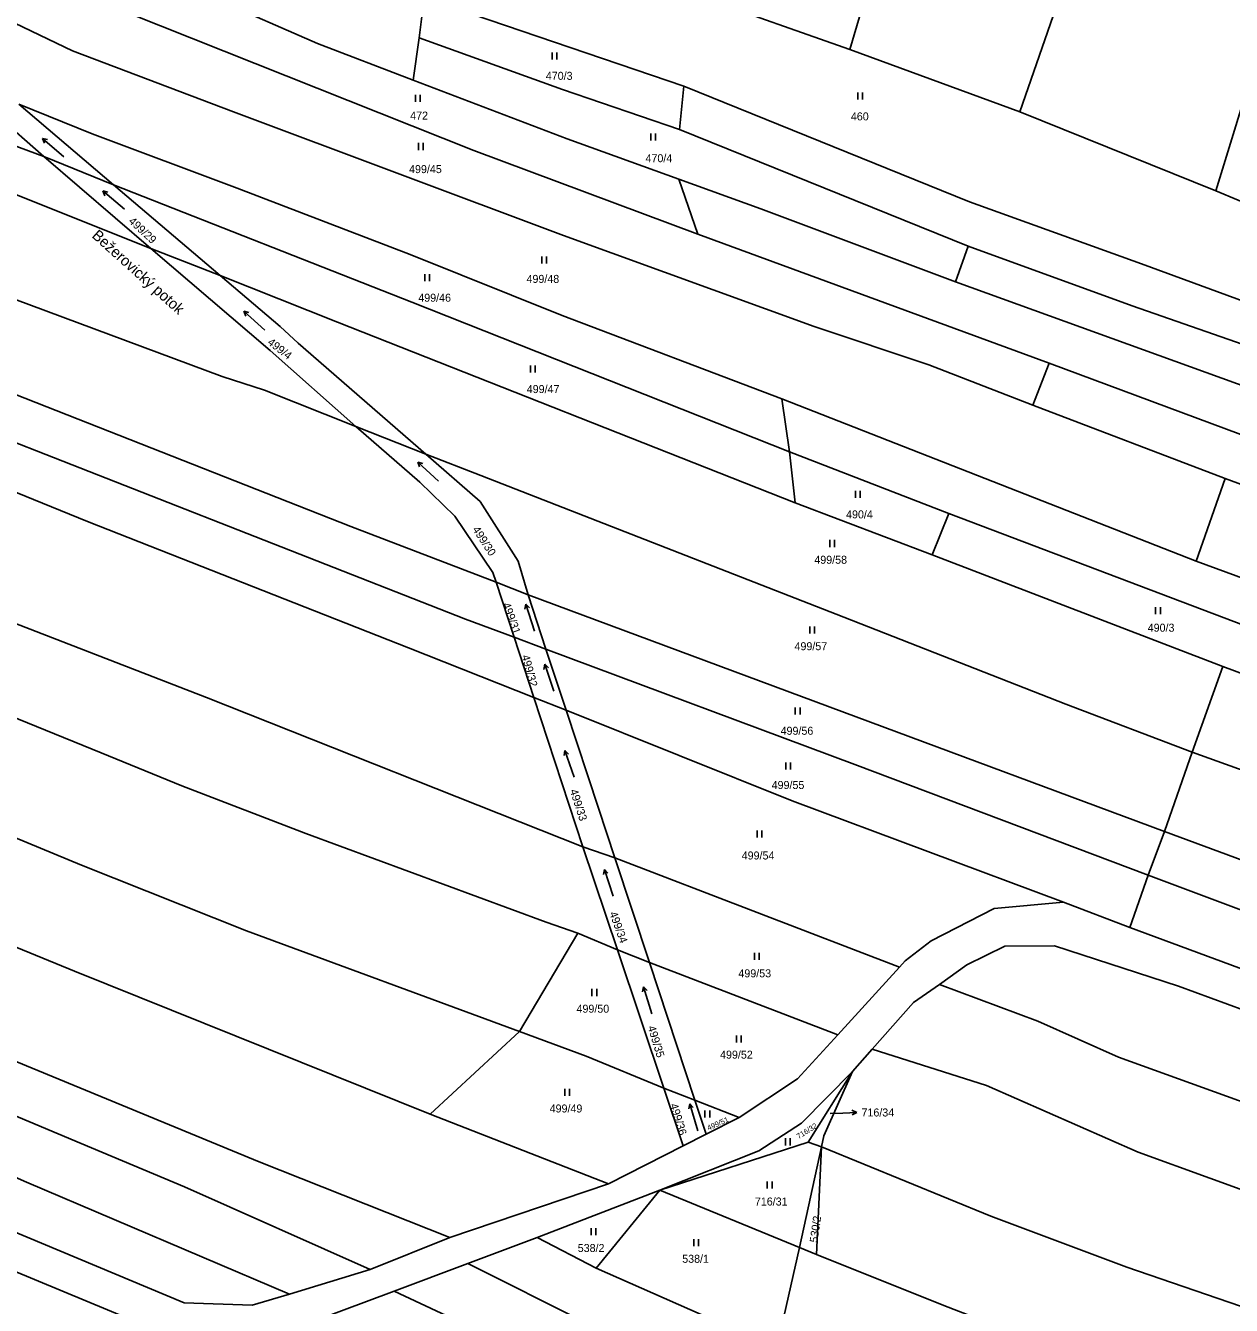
# Model space of a CAD drawing. Extents: x -7476540 to -746055, y -11317203 to -1129777.
# Drawn here: x -748441 to -748184.6, y -1130874.9 to -1130603 of the extents above; entities that cross this region are included whole.
import ezdxf

# ---------------------------------------------------------------- set-up
doc = ezdxf.new("R2010")
doc.units = 0
for name, color, linetype in [('Hranice parcel', 7, 'Continuous'), ('Parcelní čísla', 7, 'Continuous'), ('Pop  PČ popisy', 7, 'Continuous'), ('Značky kultur', 7, 'Continuous')]:
    doc.layers.add(name, color=color, linetype=linetype)

msp = doc.modelspace()

# ---------------------------------------------------------------- linework, layer by layer
at = {"layer": 'Hranice parcel'}
for p, q in [((-748306.94, -1130593.5), (-748265.75, -1130608.04)), ((-748357.28, -1130605.56), (-748356.21, -1130597)), ((-748356.21, -1130597), (-748301.06, -1130615.84)), ((-748358.56, -1130614.59), (-748357.28, -1130605.56)), ((-748265.75, -1130608.04), (-748229.57, -1130621.28)), ((-748455.69, -1130614.55), (-748437.09, -1130630.78)), ((-748301.06, -1130615.84), (-748301.92, -1130625.04)), ((-748422.31, -1130636.78), (-748442.43, -1130619.67)), ((-748229.57, -1130621.28), (-748187.91, -1130638.09)), ((-748301.92, -1130625.04), (-748240.56, -1130649.85)), ((-748437.09, -1130630.78), (-748422.31, -1130636.78)), ((-748437.09, -1130630.78), (-748414.36, -1130650.31)), ((-748399.6, -1130656.07), (-748422.31, -1130636.78)), ((-748302.08, -1130635.58), (-748298.06, -1130647.31)), ((-748187.91, -1130638.09), (-748171.3, -1130645.09)), ((-748298.06, -1130647.31), (-748223.38, -1130674.7)), ((-748399.6, -1130656.07), (-748414.36, -1130650.31)), ((-748240.56, -1130649.85), (-748243.24, -1130657.42)), ((-748223.38, -1130674.7), (-748226.83, -1130683.61)), ((-748192.08, -1130716.76), (-748280.18, -1130682.27)), ((-748280.18, -1130682.27), (-748278.6, -1130693.52)), ((-748226.83, -1130683.61), (-748185.93, -1130699.2)), ((-748370.74, -1130688.16), (-748355.87, -1130694.01)), ((-748278.6, -1130693.52), (-748244.7, -1130706.67)), ((-748278.6, -1130693.52), (-748277.39, -1130704.35)), ((-748185.93, -1130699.2), (-748192.08, -1130716.76)), ((-748277.39, -1130704.35), (-748248.26, -1130715.42)), ((-748244.7, -1130706.67), (-748248.26, -1130715.42)), ((-748248.26, -1130715.42), (-748186.46, -1130739.14)), ((-748340.95, -1130721.23), (-748334.14, -1130723.95)), ((-748340.95, -1130721.23), (-748337.1, -1130732.95)), ((-748330.34, -1130735.47), (-748334.14, -1130723.95)), ((-748337.1, -1130732.95), (-748330.34, -1130735.47)), ((-748337.1, -1130732.95), (-748332.9, -1130745.74)), ((-748326.07, -1130748.44), (-748330.34, -1130735.47)), ((-748186.46, -1130739.14), (-748192.95, -1130757.36)), ((-748186.46, -1130739.14), (-748156.81, -1130750.21)), ((-748332.9, -1130745.74), (-748326.07, -1130748.44)), ((-748322.49, -1130777.44), (-748332.9, -1130745.74)), ((-748198.84, -1130774.24), (-748192.95, -1130757.36)), ((-748202.3, -1130783.51), (-748198.84, -1130774.24)), ((-748322.49, -1130777.44), (-748315.72, -1130779.81)), ((-748322.49, -1130777.44), (-748315.11, -1130799.35)), ((-748308.36, -1130802.04), (-748315.72, -1130779.81)), ((-748255.16, -1130803.06), (-748315.72, -1130779.81)), ((-748206.22, -1130794.61), (-748202.3, -1130783.51)), ((-748206.22, -1130794.61), (-748220.29, -1130789.23)), ((-748323.6, -1130795.85), (-748336, -1130816.73)), ((-748323.6, -1130795.85), (-748315.11, -1130799.35)), ((-748315.11, -1130799.35), (-748308.36, -1130802.04)), ((-748315.11, -1130799.35), (-748305.32, -1130828.72)), ((-748298.68, -1130831.28), (-748308.36, -1130802.04)), ((-748268.27, -1130817.4), (-748308.36, -1130802.04)), ((-748255.16, -1130803.06), (-748268.27, -1130817.4)), ((-748336, -1130816.73), (-748354.99, -1130834.29)), ((-748260.98, -1130820.46), (-748265.19, -1130825.19)), ((-748274.62, -1130840.2), (-748265.19, -1130825.19)), ((-748305.32, -1130828.72), (-748298.68, -1130831.28)), ((-748305.32, -1130828.72), (-748301.18, -1130841.02)), ((-748296.28, -1130838.54), (-748298.68, -1130831.28)), ((-748289.25, -1130834.98), (-748298.68, -1130831.28)), ((-748354.99, -1130834.29), (-748317.07, -1130849.07)), ((-748289.25, -1130834.98), (-748296.28, -1130838.54)), ((-748296.28, -1130838.54), (-748301.18, -1130841.02)), ((-748301.18, -1130841.02), (-748317.07, -1130849.07)), ((-748274.62, -1130840.2), (-748306.12, -1130850.42)), ((-748271.76, -1130841.22), (-748276.46, -1130862.6)), ((-748271.76, -1130841.22), (-748274.62, -1130840.2)), ((-748272.8, -1130864.07), (-748271.76, -1130841.22)), ((-748317.07, -1130849.07), (-748350.77, -1130860.5)), ((-748332.19, -1130860.47), (-748306.12, -1130850.42)), ((-748306.12, -1130850.42), (-748319.69, -1130866.98)), ((-748276.46, -1130862.6), (-748306.12, -1130850.42)), ((-748350.77, -1130860.5), (-748367.71, -1130867.32)), ((-748346.93, -1130865.99), (-748332.19, -1130860.47)), ((-748319.69, -1130866.98), (-748332.19, -1130860.47)), ((-748276.46, -1130862.6), (-748281.3, -1130883.89)), ((-748276.46, -1130862.6), (-748272.8, -1130864.07)), ((-748362.61, -1130871.86), (-748346.93, -1130865.99)), ((-748367.71, -1130867.32), (-748384.89, -1130872.51)), ((-748281.3, -1130883.89), (-748319.69, -1130866.98)), ((-748379.12, -1130878.04), (-748362.61, -1130871.86))]:
    msp.add_line(p, q, dxfattribs=at)
for points in [[(-748265.75, -1130608.04), (-748247.9, -1130547.61), (-748233.17, -1130503.73)], [(-748229.57, -1130621.28), (-748216.56, -1130583.68), (-748204.16, -1130547.99), (-748197.06, -1130528.56)], [(-748187.91, -1130638.09), (-748178.92, -1130608.81), (-748161.77, -1130554.58)], [(-748485.04, -1130582.73), (-748469.61, -1130589.74), (-748431.04, -1130608.33), (-748396.79, -1130621.28), (-748326.64, -1130647.59), (-748273.31, -1130666.87), (-748248.94, -1130675.02), (-748226.83, -1130683.61)], [(-748400.65, -1130597.24), (-748378.93, -1130606.77), (-748358.56, -1130614.59)], [(-748418.92, -1130600.37), (-748345.69, -1130629.51), (-748298.06, -1130647.31)], [(-748370.74, -1130688.16), (-748390.16, -1130680.44), (-748399.18, -1130677.54), (-748453.71, -1130657.26), (-748528.86, -1130627.98), (-748582.3, -1130606.18)], [(-748357.28, -1130605.56), (-748326.8, -1130616.53), (-748301.92, -1130625.04)], [(-748474.99, -1130628.2), (-748478.16, -1130615.62), (-748437.09, -1130630.78)], [(-748358.56, -1130614.59), (-748325.84, -1130627.02), (-748302.08, -1130635.58)], [(-748301.06, -1130615.84), (-748240.31, -1130640.44), (-748203.71, -1130653.58), (-748161.84, -1130668.98)], [(-748280.18, -1130682.27), (-748326.88, -1130664.57), (-748359.23, -1130651.59), (-748396.02, -1130637.54), (-748426.83, -1130625.94), (-748442.43, -1130619.67)], [(-748340.95, -1130721.23), (-748371.81, -1130709.41), (-748485.85, -1130664.58), (-748534.39, -1130645.25), (-748586.34, -1130622.61)], [(-748414.36, -1130650.31), (-748452.93, -1130634.95), (-748474.99, -1130628.2)], [(-748337.1, -1130732.95), (-748347.47, -1130729.08), (-748459.12, -1130685.32), (-748534.17, -1130654.92), (-748588.68, -1130630.55)], [(-748422.31, -1130636.78), (-748358.85, -1130661.76), (-748278.6, -1130693.52)], [(-748302.08, -1130635.58), (-748284.66, -1130641.91), (-748243.24, -1130657.42)], [(-748332.9, -1130745.74), (-748359.6, -1130735.19), (-748427.81, -1130708.36), (-748542.83, -1130661.55), (-748593.74, -1130637.98)], [(-748414.36, -1130650.31), (-748389.01, -1130672.04), (-748370.74, -1130688.16)], [(-748240.56, -1130649.85), (-748205.74, -1130662.52), (-748166.46, -1130676.19), (-748149.75, -1130682.7), (-748123.01, -1130692.38), (-748074.3, -1130710.72), (-748054.6, -1130717.75), (-748018.25, -1130732.85), (-747986.44, -1130749.26)], [(-748399.6, -1130656.07), (-748374.67, -1130665.95), (-748277.39, -1130704.35)], [(-748355.87, -1130694.01), (-748383.04, -1130670.46), (-748386.85, -1130666.91), (-748399.6, -1130656.07)], [(-748243.24, -1130657.42), (-748166.65, -1130685.11), (-748094.37, -1130712.93), (-748058.72, -1130726.42), (-748019.1, -1130743.55), (-747990.16, -1130757.72)], [(-748606.79, -1130664), (-748593.41, -1130669.82), (-748555.79, -1130686.41), (-748521.14, -1130699.97), (-748463.67, -1130722.09), (-748402.55, -1130745.71), (-748322.49, -1130777.44)], [(-748223.38, -1130674.7), (-748160.68, -1130697.99), (-748104.99, -1130718.13), (-748087.93, -1130725.07), (-748056.46, -1130736.89), (-748027.2, -1130749.04), (-747994, -1130766.24)], [(-748370.74, -1130688.16), (-748357.13, -1130699.98), (-748349.74, -1130707.22), (-748341.63, -1130719.17), (-748340.95, -1130721.23)], [(-748591.33, -1130689.59), (-748556.18, -1130705.09), (-748511.54, -1130723.13), (-748468.11, -1130739.92), (-748424.93, -1130757.48), (-748407.79, -1130764.49), (-748381.4, -1130774.63), (-748330.32, -1130793.51), (-748323.6, -1130795.85)], [(-748334.14, -1130723.95), (-748336.28, -1130716.76), (-748344.32, -1130704.11), (-748355.87, -1130694.01)], [(-748192.95, -1130757.36), (-748219.82, -1130747.15), (-748267.04, -1130728.69), (-748344.18, -1130698.6), (-748355.87, -1130694.01)], [(-748185.93, -1130699.2), (-748116.35, -1130724.81), (-748065.1, -1130743.37), (-748028.39, -1130758.32), (-747998.62, -1130776.08)], [(-748244.7, -1130706.67), (-748172.71, -1130733.91), (-748157.04, -1130739.82)], [(-748600.62, -1130708.93), (-748572.02, -1130722.05), (-748553.57, -1130730.11), (-748529.63, -1130739.69), (-748429.06, -1130781.38), (-748394.01, -1130795.35), (-748336, -1130816.73)], [(-748192.08, -1130716.76), (-748141.67, -1130735.26), (-748110.72, -1130746.5), (-748083.73, -1130756.86), (-748044.13, -1130772.48), (-748036.15, -1130775.89), (-748006.3, -1130791.42)], [(-748198.84, -1130774.24), (-748264.42, -1130749.83), (-748334.14, -1130723.95)], [(-748609.37, -1130729.04), (-748586.47, -1130739.97), (-748565.25, -1130748.92), (-748478.86, -1130784.11), (-748430.59, -1130803.91), (-748354.99, -1130834.29)], [(-748202.3, -1130783.51), (-748264.68, -1130759.98), (-748330.34, -1130735.47)], [(-748617.75, -1130748.36), (-748594.66, -1130762.19), (-748574.85, -1130769.98), (-748508.41, -1130796.48), (-748448.56, -1130820.81), (-748391.34, -1130844.41), (-748350.77, -1130860.5)], [(-748315.72, -1130779.81), (-748319.21, -1130769.27), (-748326.07, -1130748.44)], [(-748220.29, -1130789.23), (-748278.03, -1130767.72), (-748326.07, -1130748.44)], [(-748638.72, -1130751.72), (-748602.16, -1130770.3), (-748522.97, -1130802.41), (-748472.42, -1130822.39), (-748429.14, -1130840.54), (-748407.16, -1130849.74), (-748367.71, -1130867.32)], [(-748192.95, -1130757.36), (-748149.26, -1130773.11), (-748117.42, -1130785.04), (-748079.7, -1130799.19), (-748023.6, -1130824.38)], [(-748641.83, -1130766.14), (-748594.17, -1130785.58), (-748542.67, -1130805.9), (-748476.15, -1130833.14), (-748440.81, -1130848.76), (-748384.89, -1130872.51)], [(-748384.89, -1130872.51), (-748392.79, -1130874.89), (-748407.29, -1130874.39), (-748504.41, -1130833.78), (-748556.44, -1130811.2), (-748636.94, -1130777.36), (-748641.83, -1130766.14)], [(-748198.84, -1130774.24), (-748124.83, -1130801.55), (-748095.68, -1130812.38), (-748052.4, -1130830.31), (-748030.93, -1130840.93)], [(-748202.3, -1130783.51), (-748146.21, -1130804.55), (-748090.95, -1130825.26), (-748056.18, -1130839.2), (-748035.09, -1130849.72)], [(-748640.02, -1130785.32), (-748543.51, -1130825.81), (-748464.71, -1130858.77), (-748407.23, -1130882.69)], [(-748220.29, -1130789.23), (-748235.03, -1130790.57), (-748248.44, -1130797.43), (-748253.94, -1130801.72), (-748255.16, -1130803.06)], [(-748042.25, -1130857.8), (-748097.77, -1130834.89), (-748116.18, -1130827.89), (-748206.22, -1130794.61)], [(-748246.71, -1130806.7), (-748240.86, -1130802.57), (-748232.82, -1130798.59), (-748222.25, -1130798.5), (-748195.87, -1130807.09), (-748171.55, -1130816.01), (-748091.95, -1130844.69), (-748061.9, -1130856.72), (-748042.73, -1130867.52)], [(-748260.98, -1130820.46), (-748252.18, -1130810.57), (-748246.71, -1130806.7)], [(-748037.84, -1130894.2), (-748054.55, -1130885.78), (-748102.13, -1130862.63), (-748153.66, -1130841.78), (-748178, -1130833.24), (-748208.63, -1130822.17), (-748225.74, -1130814.53), (-748246.71, -1130806.7)], [(-748305.32, -1130828.72), (-748321.79, -1130821.98), (-748336, -1130816.73)], [(-748268.27, -1130817.4), (-748276.84, -1130826.78), (-748289.25, -1130834.98)], [(-748027.06, -1130916.24), (-748075.79, -1130892.9), (-748112.36, -1130877.79), (-748129.42, -1130870.81), (-748173.97, -1130853.4), (-748204.44, -1130842.38), (-748236.71, -1130828.16), (-748260.98, -1130820.46)], [(-748306.12, -1130850.42), (-748285.08, -1130842.06), (-748276.01, -1130836.18), (-748265.19, -1130825.19)], [(-748265.19, -1130825.19), (-748271.25, -1130838.88), (-748271.76, -1130841.22)], [(-748271.76, -1130841.22), (-748235.77, -1130855.93), (-748206.84, -1130866.81), (-748165.74, -1130880.87), (-748130.12, -1130894.99), (-748094.02, -1130910.31), (-748045.92, -1130930.72), (-748002.03, -1130951.62), (-747975.69, -1130968.08), (-747956.74, -1130979.41)], [(-748283.22, -1130895.4), (-748321.83, -1130878.64), (-748346.93, -1130865.99)], [(-747973.45, -1130994.17), (-747986.3, -1130986.83), (-748025.01, -1130962.88), (-748060.2, -1130946.83), (-748098.9, -1130931.91), (-748130.17, -1130918.61), (-748198.42, -1130893.2), (-748245.75, -1130874.96), (-748272.8, -1130864.07)], [(-748285.26, -1130906.35), (-748321.46, -1130891.15), (-748362.61, -1130871.86)]]:
    msp.add_lwpolyline(points, dxfattribs=at)
at = {"layer": 'Pop  PČ popisy'}
for p, q in [((-748269.9, -1130834.17), (-748267.26, -1130834.05)), ((-748267.26, -1130834.05), (-748264.26, -1130833.89)), ((-748264.26, -1130833.89), (-748265.29, -1130833.45)), ((-748264.26, -1130833.89), (-748265.24, -1130834.45))]:
    msp.add_line(p, q, dxfattribs=at)
at = {"layer": 'Značky kultur'}
for p, q in [((-748329, -1130610.17), (-748329, -1130608.67)), ((-748328, -1130610.17), (-748328, -1130608.67)), ((-748358.11, -1130619.19), (-748358.11, -1130617.69)), ((-748357.11, -1130619.19), (-748357.11, -1130617.69)), ((-748264.03, -1130618.7), (-748264.03, -1130617.2)), ((-748263.03, -1130618.7), (-748263.03, -1130617.2)), ((-748308.08, -1130627.38), (-748308.08, -1130625.88)), ((-748307.08, -1130627.38), (-748307.08, -1130625.88)), ((-748432.86, -1130630.87), (-748437.39, -1130626.93)), ((-748437.39, -1130626.93), (-748436.98, -1130627.95)), ((-748437.39, -1130626.93), (-748436.33, -1130627.2)), ((-748357.48, -1130629.4), (-748357.48, -1130627.9)), ((-748356.48, -1130629.4), (-748356.48, -1130627.9)), ((-748419.96, -1130641.96), (-748424.56, -1130638.1)), ((-748424.56, -1130638.1), (-748424.13, -1130639.12)), ((-748424.56, -1130638.1), (-748423.48, -1130638.35)), ((-748331.23, -1130653.52), (-748331.23, -1130652.02)), ((-748330.23, -1130653.52), (-748330.23, -1130652.02)), ((-748356.1, -1130657.3), (-748356.1, -1130655.8)), ((-748355.1, -1130657.3), (-748355.1, -1130655.8)), ((-748390.12, -1130667.69), (-748394.58, -1130663.68)), ((-748394.58, -1130663.68), (-748394.19, -1130664.7)), ((-748394.58, -1130663.68), (-748393.52, -1130663.96)), ((-748333.62, -1130676.71), (-748333.62, -1130675.21)), ((-748332.62, -1130676.71), (-748332.62, -1130675.21)), ((-748353.2, -1130699.79), (-748357.59, -1130695.7)), ((-748357.59, -1130695.7), (-748357.22, -1130696.73)), ((-748357.59, -1130695.7), (-748356.53, -1130696)), ((-748264.57, -1130703.34), (-748264.57, -1130701.84)), ((-748263.57, -1130703.34), (-748263.57, -1130701.84)), ((-748270, -1130713.77), (-748270, -1130712.27)), ((-748269, -1130713.77), (-748269, -1130712.27)), ((-748334.65, -1130725.92), (-748334.83, -1130727)), ((-748332.8, -1130731.62), (-748334.65, -1130725.92)), ((-748334.65, -1130725.92), (-748333.88, -1130726.69)), ((-748200.72, -1130728.01), (-748200.72, -1130726.51)), ((-748199.72, -1130728.01), (-748199.72, -1130726.51)), ((-748274.27, -1130732.14), (-748274.27, -1130730.64)), ((-748273.27, -1130732.14), (-748273.27, -1130730.64)), ((-748330.62, -1130738.69), (-748330.78, -1130739.78)), ((-748328.67, -1130744.37), (-748330.62, -1130738.69)), ((-748330.62, -1130738.69), (-748329.83, -1130739.46)), ((-748277.33, -1130749.33), (-748277.33, -1130747.83)), ((-748276.33, -1130749.33), (-748276.33, -1130747.83)), ((-748326.33, -1130756.98), (-748326.49, -1130758.07)), ((-748324.38, -1130762.66), (-748326.33, -1130756.98)), ((-748326.33, -1130756.98), (-748325.54, -1130757.75)), ((-748279.34, -1130761.04), (-748279.34, -1130759.54)), ((-748278.34, -1130761.04), (-748278.34, -1130759.54)), ((-748285.46, -1130775.52), (-748285.46, -1130774.02)), ((-748284.46, -1130775.52), (-748284.46, -1130774.02)), ((-748317.93, -1130782.27), (-748318.11, -1130783.35)), ((-748316.08, -1130787.97), (-748317.93, -1130782.27)), ((-748317.93, -1130782.27), (-748317.16, -1130783.04)), ((-748286.01, -1130801.5), (-748286.01, -1130800)), ((-748285.01, -1130801.5), (-748285.01, -1130800)), ((-748320.56, -1130809.17), (-748320.56, -1130807.67)), ((-748319.56, -1130809.17), (-748319.56, -1130807.67)), ((-748309.59, -1130807.23), (-748309.79, -1130808.31)), ((-748307.84, -1130812.97), (-748309.59, -1130807.23)), ((-748309.59, -1130807.23), (-748308.83, -1130808.02)), ((-748289.81, -1130819.04), (-748289.81, -1130817.54)), ((-748288.81, -1130819.04), (-748288.81, -1130817.54)), ((-748326.34, -1130830.37), (-748326.34, -1130828.87)), ((-748325.34, -1130830.37), (-748325.34, -1130828.87)), ((-748299.79, -1130832.07), (-748299.99, -1130833.15)), ((-748298.04, -1130837.81), (-748299.79, -1130832.07)), ((-748299.79, -1130832.07), (-748299.03, -1130832.86)), ((-748296.54, -1130835), (-748296.54, -1130833.5)), ((-748295.54, -1130835), (-748295.54, -1130833.5)), ((-748279.43, -1130840.91), (-748279.43, -1130839.41)), ((-748278.43, -1130840.91), (-748278.43, -1130839.41)), ((-748283.28, -1130850.08), (-748283.28, -1130848.58)), ((-748282.28, -1130850.08), (-748282.28, -1130848.58)), ((-748320.76, -1130860.02), (-748320.76, -1130858.52)), ((-748319.76, -1130860.02), (-748319.76, -1130858.52)), ((-748298.92, -1130862.31), (-748298.92, -1130860.81)), ((-748297.92, -1130862.31), (-748297.92, -1130860.81))]:
    msp.add_line(p, q, dxfattribs=at)

# ---------------------------------------------------------------- texts
at = {"layer": 'Parcelní čísla'}
for s, p in [('470/3', (-748330.38, -1130614.49)), ('472', (-748359.21, -1130622.94)), ('460', (-748265.52, -1130623.11)), ('470/4', (-748309.18, -1130632)), ('499/45', (-748359.45, -1130634.31)), ('499/48', (-748334.48, -1130657.64)), ('499/46', (-748357.49, -1130661.64)), ('499/47', (-748334.43, -1130681.05)), ('490/4', (-748266.54, -1130707.68)), ('499/58', (-748273.29, -1130717.32)), ('490/3', (-748202.41, -1130731.76)), ('499/57', (-748277.5, -1130735.69)), ('499/56', (-748280.46, -1130753.66)), ('499/55', (-748282.36, -1130765.18)), ('499/54', (-748288.73, -1130780.16)), ('499/53', (-748289.43, -1130805.2)), ('499/50', (-748323.85, -1130812.72)), ('499/52', (-748293.33, -1130822.48)), ('499/49', (-748329.56, -1130833.92)), ('716/34', (-748263.26, -1130834.77)), ('716/31', (-748285.93, -1130853.69)), ('538/2', (-748323.59, -1130863.57)), ('538/1', (-748301.38, -1130865.86))]:
    msp.add_text(s, height=1.7, dxfattribs=at).set_placement(p)
for s, height, rotation, p in [('499/29', 1.7, 317, (-748419.22, -1130644.71)), ('499/4', 1.7, 322, (-748389.69, -1130670.54)), ('499/30', 1.7, 303, (-748346.06, -1130710.03)), ('499/31', 1.7, 290, (-748339.62, -1130725.92)), ('499/32', 1.7, 285, (-748335.53, -1130736.92)), ('499/33', 1.7, 288, (-748325.29, -1130765.52)), ('499/34', 1.7, 290, (-748316.89, -1130791.58)), ('499/35', 1.7, 287, (-748308.74, -1130815.76)), ('499/36', 1.7, 287, (-748304.01, -1130832.28)), ('499/51', 1.14, 24, (-748295.77, -1130837.79)), ('716/32', 1.14, 32, (-748276.62, -1130839.6)), ('530/2', 1.7, 82, (-748272.62, -1130861.65))]:
    msp.add_text(s, height=height, rotation=rotation, dxfattribs=at).set_placement(p)
at = {"layer": 'Pop  PČ popisy'}
msp.add_text('Bežerovický potok', height=2.3, rotation=318, dxfattribs=at).set_placement((-748427.04, -1130647.82))

doc.saveas('drawing.dxf')
